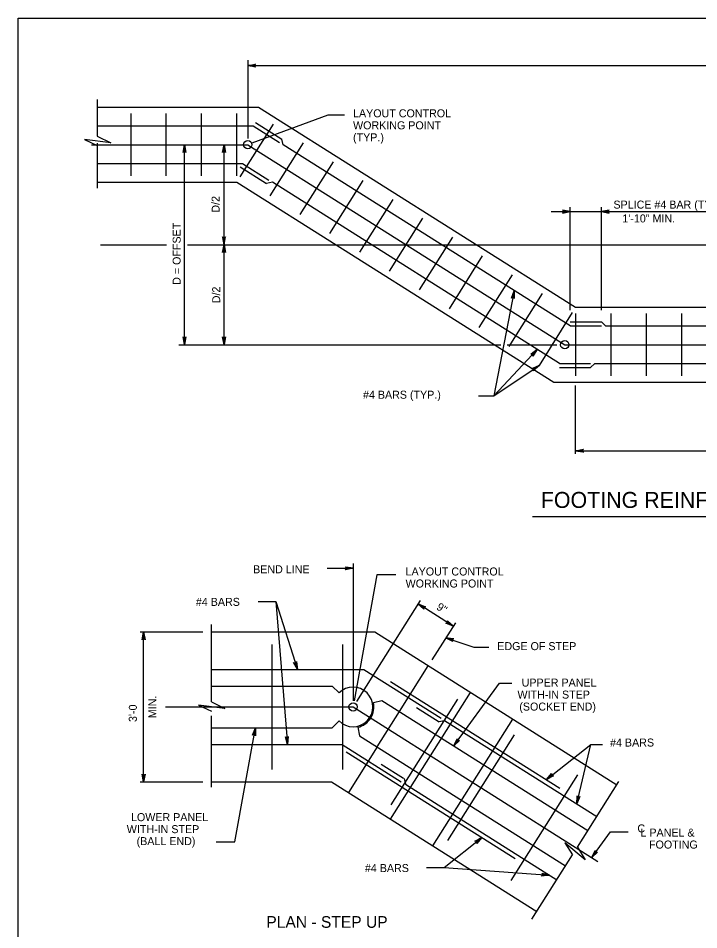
# Model space of a CAD drawing. Extents: x 3385 to 6532, y -616 to 1166.
# Drawn here: x 4642.3 to 4903.8, y -387.3 to -37.3 of the extents above; entities that cross this region are included whole.
import ezdxf

# ---------------------------------------------------------------- set-up
doc = ezdxf.new("R2010")
doc.units = 0
doc.layers.add('1', color=7, linetype='Continuous')
doc.layers.add('2', color=7, linetype='Continuous')

msp = doc.modelspace()

# ---------------------------------------------------------------- linework, layer by layer
at = {"layer": '1'}
for p, q in [((4730.55, -53.39), (4730.55, -83.46)), ((4730.55, -55.48), (5262.17, -55.48)), ((4672.73, -68.46), (4672.73, -82.65)), ((4672.73, -71.46), (4734.71, -71.46)), ((4734.71, -71.46), (4856.52, -148.26)), ((4685.68, -97.86), (4685.68, -73.86)), ((4699.25, -97.86), (4699.25, -73.86)), ((4712.82, -97.86), (4712.82, -73.86)), ((4726.39, -97.86), (4726.39, -73.86)), ((4761.26, -74.48), (4732.05, -85.3)), ((4767.72, -74.48), (4761.26, -74.48)), ((4672.73, -78.66), (4732.63, -78.66)), ((4727.67, -98.23), (4740.47, -77.93)), ((4732.63, -78.66), (4742.78, -85.06)), ((4733.48, -77.3), (4743.64, -83.7)), ((4744.14, -85.91), (4743.64, -83.7)), ((4670.51, -85.86), (4730.55, -85.86)), ((4672.73, -85.29), (4672.73, -102.52)), ((4706.23, -162.66), (4706.23, -85.86)), ((4721.42, -162.66), (4721.42, -85.86)), ((4730.55, -85.86), (4852.36, -162.66)), ((4730.55, -85.86), (4730.55, -85.86)), ((4739.14, -105.46), (4751.94, -85.16)), ((4854.44, -155.46), (4744.14, -85.91)), ((4672.73, -93.06), (4728.47, -93.06)), ((4727.61, -94.41), (4737.77, -100.81)), ((4728.47, -93.06), (4738.62, -99.46)), ((4750.62, -112.7), (4763.42, -92.39)), ((4672.73, -100.26), (4726.39, -100.26)), ((4726.39, -100.26), (4848.2, -177.06)), ((4739.98, -100.31), (4737.77, -100.81)), ((4850.28, -169.86), (4739.98, -100.31)), ((4762.09, -119.93), (4774.89, -99.63)), ((4773.57, -127.17), (4786.37, -106.86)), ((4847.16, -111.55), (4932.51, -111.55)), ((4854.44, -149.35), (4854.44, -109.88)), ((4866.44, -149.35), (4866.44, -109.88)), ((4785.04, -134.4), (4797.84, -114.1)), ((4796.51, -141.64), (4809.31, -121.33)), ((4673.94, -124.26), (4699.26, -124.26)), ((4707.43, -124.26), (5285.01, -124.26)), ((4807.99, -148.87), (4820.79, -128.57)), ((4819.46, -156.1), (4832.26, -135.8)), ((4832.96, -141.91), (4825.08, -182.24)), ((4830.94, -163.34), (4843.74, -143.04)), ((4855.24, -150.29), (4842.44, -170.59)), ((4856.52, -148.26), (4992.2, -148.26)), ((4854.44, -153.86), (4866.44, -153.86)), ((4856.52, -150.66), (4856.52, -174.66)), ((4868.04, -155.46), (4866.44, -153.86)), ((4870.08, -150.66), (4870.08, -174.66)), ((4883.65, -150.66), (4883.65, -174.66)), ((4897.21, -150.66), (4897.21, -174.66)), ((4854.44, -155.46), (4866.44, -155.46)), ((4868.04, -155.46), (4994.28, -155.46)), ((4704, -162.66), (4827.79, -162.66)), ((4825.08, -182.24), (4841.73, -164.47)), ((4830.2, -162.66), (4849.32, -162.66)), ((4852.36, -162.66), (4996.36, -162.66)), ((4852.36, -162.66), (4852.36, -162.66)), ((4825.08, -182.24), (4842.44, -170.59)), ((4850.28, -169.86), (4862.28, -169.86)), ((4850.28, -171.46), (4862.28, -171.46)), ((4863.88, -169.86), (4862.28, -171.46)), ((4863.88, -169.86), (4998.44, -169.86)), ((4848.2, -177.06), (5000.52, -177.06)), ((4856.52, -204.62), (4856.52, -178.37)), ((4819.25, -182.24), (4825.08, -182.24)), ((4856.52, -203.38), (4992.2, -203.38)), ((4839.99, -228.57), (5138.02, -228.57)), ((4761.01, -248.48), (4771.01, -248.48)), ((4771.01, -246.71), (4771.01, -299.34)), ((4780.13, -251.06), (4771.43, -299.38)), ((4787.47, -251.06), (4780.13, -251.06)), ((4734.54, -261.31), (4741.35, -261.31)), ((4741.35, -261.31), (4745.78, -316.14)), ((4741.35, -261.31), (4749.6, -287.34)), ((4796.78, -260.86), (4772.29, -299.71)), ((4809.49, -270.71), (4795.95, -262.17)), ((4810.32, -269.39), (4801.3, -283.69)), ((4689.15, -272.94), (4713.23, -272.94)), ((4690.54, -330.54), (4690.54, -272.94)), ((4716.55, -299.84), (4716.55, -270.06)), ((4716.55, -272.94), (4779.33, -272.94)), ((4779.33, -272.94), (4872.36, -331.59)), ((4806.65, -275.15), (4817.41, -278.73)), ((4739.97, -325.74), (4739.97, -277.74)), ((4767.11, -325.74), (4767.11, -277.74)), ((4817.41, -278.73), (4823.12, -278.73)), ((4788.81, -303.5), (4799.9, -285.91)), ((4716.55, -287.34), (4775.17, -287.34)), ((4775.17, -287.34), (4804.87, -306.07)), ((4716.55, -293.74), (4763.01, -293.74)), ((4763.01, -293.74), (4765.63, -296.37)), ((4785.43, -291.91), (4850.4, -332.87)), ((4809.69, -316.66), (4827.21, -292.59)), ((4827.21, -292.59), (4832.03, -292.59)), ((4785.42, -344.88), (4816.14, -296.15)), ((4778.81, -299.97), (4782.04, -299.24)), ((4782.05, -299.24), (4861.24, -349.17)), ((4785.6, -339.32), (4811.2, -298.71)), ((4698.94, -301.74), (4771.01, -301.74)), ((4771.01, -301.74), (4865.08, -361.05)), ((4771.01, -301.74), (4771.01, -301.74)), ((4780.27, -317.05), (4788.81, -303.5)), ((4795.43, -302), (4804.02, -307.42)), ((4716.55, -332.53), (4716.55, -305.09)), ((4763.01, -309.74), (4765.63, -307.12)), ((4801.66, -355.12), (4832.39, -306.39)), ((4803.99, -307.39), (4806.19, -306.9)), ((4806.19, -306.9), (4864.66, -343.76)), ((4716.55, -309.74), (4763.01, -309.74)), ((4725.54, -353.54), (4733.45, -309.74)), ((4772.78, -309.54), (4773.51, -312.78)), ((4773.51, -312.78), (4852.68, -362.7)), ((4807.38, -353.05), (4832.98, -312.44)), ((4716.55, -316.14), (4766.85, -316.14)), ((4766.85, -316.14), (4789.51, -330.43)), ((4780.27, -317.05), (4769.18, -334.64)), ((4845.27, -329.64), (4862.37, -316.15)), ((4856.95, -338.9), (4862.37, -316.15)), ((4862.37, -316.15), (4866.87, -316.15)), ((4768.35, -318.99), (4833.32, -359.95)), ((4781.77, -323.67), (4790.36, -329.08)), ((4831.75, -368.41), (4857.35, -327.8)), ((4689.15, -330.54), (4713.23, -330.54)), ((4716.55, -330.54), (4762.69, -330.54)), ((4762.69, -330.54), (4841.56, -380.27)), ((4790.61, -329.24), (4791.11, -331.44)), ((4791.11, -331.44), (4849.26, -368.1)), ((4857.19, -355.57), (4873.11, -330.4)), ((4862.76, -359.59), (4869.94, -349.71)), ((4869.94, -349.71), (4876.71, -349.71)), ((4805.96, -363.37), (4820.53, -351.88)), ((4718.41, -353.54), (4725.54, -353.54)), ((4839.72, -383.19), (4855.31, -358.54)), ((4799.15, -363.37), (4805.96, -363.37)), ((4805.96, -363.37), (4846.41, -366.31))]:
    msp.add_line(p, q, dxfattribs=at)
for points in [[(4730.55, -55.48), (4733.53, -54.92), (4733.3, -55.08), (4733.18, -55.28), (4733.15, -55.48), (4733.18, -55.68), (4733.3, -55.88), (4733.53, -56.04), (4730.55, -55.48), (4733.3, -55.88), (4733.18, -55.68), (4730.55, -55.48), (4733.15, -55.48), (4733.18, -55.28), (4730.55, -55.48), (4733.3, -55.08)], [(4672.73, -82.65), (4677.92, -85.19), (4667.77, -83.81), (4672.73, -86.17)], [(4706.23, -85.86), (4706.79, -88.84), (4706.63, -88.61), (4706.43, -88.49), (4706.23, -88.46), (4706.03, -88.49), (4705.83, -88.61), (4705.67, -88.84), (4706.23, -85.86), (4705.83, -88.61), (4706.03, -88.49), (4706.23, -85.86), (4706.23, -88.46), (4706.43, -88.49), (4706.23, -85.86), (4706.63, -88.61)], [(4721.42, -85.86), (4721.98, -88.84), (4721.82, -88.61), (4721.62, -88.49), (4721.42, -88.46), (4721.22, -88.49), (4721.02, -88.61), (4720.86, -88.84), (4721.42, -85.86), (4721.02, -88.61), (4721.22, -88.49), (4721.42, -85.86), (4721.42, -88.46), (4721.62, -88.49), (4721.42, -85.86), (4721.82, -88.61)], [(4854.44, -111.55), (4851.46, -110.99), (4851.69, -111.15), (4851.81, -111.35), (4851.84, -111.55), (4851.81, -111.75), (4851.69, -111.95), (4851.46, -112.11), (4854.44, -111.55), (4851.69, -111.95), (4851.81, -111.75), (4854.44, -111.55), (4851.84, -111.55), (4851.81, -111.35), (4854.44, -111.55), (4851.69, -111.15)], [(4866.44, -111.55), (4869.43, -112.11), (4869.2, -111.95), (4869.08, -111.75), (4869.04, -111.55), (4869.08, -111.35), (4869.2, -111.15), (4869.43, -110.99), (4866.44, -111.55), (4869.2, -111.15), (4869.08, -111.35), (4866.44, -111.55), (4869.04, -111.55), (4869.08, -111.75), (4866.44, -111.55), (4869.2, -111.95)], [(4721.42, -124.26), (4721.98, -121.28), (4721.82, -121.51), (4721.62, -121.62), (4721.42, -121.66), (4721.22, -121.62), (4721.02, -121.51), (4720.86, -121.28), (4721.42, -124.26), (4721.02, -121.51), (4721.22, -121.62), (4721.42, -124.26), (4721.42, -121.66), (4721.62, -121.62), (4721.42, -124.26), (4721.82, -121.51)], [(4721.42, -124.26), (4721.98, -127.24), (4721.82, -127.01), (4721.62, -126.89), (4721.42, -126.86), (4721.22, -126.89), (4721.02, -127.01), (4720.86, -127.24), (4721.42, -124.26), (4721.02, -127.01), (4721.22, -126.89), (4721.42, -124.26), (4721.42, -126.86), (4721.62, -126.89), (4721.42, -124.26), (4721.82, -127.01)], [(4832.96, -141.91), (4832.93, -144.95), (4832.88, -144.82), (4832.82, -144.69), (4832.73, -144.61), (4832.65, -144.54), (4832.55, -144.5), (4832.46, -144.47), (4832.36, -144.46), (4832.26, -144.46), (4832.15, -144.5), (4832.04, -144.54), (4831.94, -144.64), (4831.84, -144.73), (4832.96, -141.91), (4831.94, -144.64), (4832.04, -144.54), (4832.96, -141.91), (4832.15, -144.5), (4832.26, -144.46), (4832.96, -141.91), (4832.36, -144.46), (4832.46, -144.47), (4832.96, -141.91), (4832.55, -144.5), (4832.65, -144.54), (4832.96, -141.91), (4832.73, -144.61), (4832.82, -144.69), (4832.96, -141.91), (4832.88, -144.82)], [(4706.23, -162.66), (4705.67, -159.68), (4705.83, -159.91), (4706.03, -160.02), (4706.23, -160.06), (4706.43, -160.02), (4706.63, -159.91), (4706.79, -159.68), (4706.23, -162.66), (4706.63, -159.91), (4706.43, -160.02), (4706.23, -162.66), (4706.23, -160.06), (4706.03, -160.02), (4706.23, -162.66), (4705.83, -159.91)], [(4721.42, -162.66), (4720.86, -159.68), (4721.02, -159.91), (4721.22, -160.02), (4721.42, -160.06), (4721.62, -160.02), (4721.82, -159.91), (4721.98, -159.68), (4721.42, -162.66), (4721.82, -159.91), (4721.62, -160.02), (4721.42, -162.66), (4721.42, -160.06), (4721.22, -160.02), (4721.42, -162.66), (4721.02, -159.91)], [(4841.73, -164.47), (4840.1, -167.03), (4840.12, -166.89), (4840.14, -166.75), (4840.11, -166.64), (4840.08, -166.53), (4840.02, -166.45), (4839.96, -166.37), (4839.87, -166.31), (4839.79, -166.26), (4839.67, -166.23), (4839.56, -166.21), (4839.42, -166.24), (4839.29, -166.26), (4841.73, -164.47), (4839.42, -166.24), (4839.56, -166.21), (4841.73, -164.47), (4839.67, -166.23), (4839.79, -166.26), (4841.73, -164.47), (4839.87, -166.31), (4839.96, -166.37), (4841.73, -164.47), (4840.02, -166.45), (4840.08, -166.53), (4841.73, -164.47), (4840.11, -166.64), (4840.14, -166.75), (4841.73, -164.47), (4840.12, -166.89)], [(4842.44, -170.59), (4840.27, -172.72), (4840.38, -172.46), (4840.36, -172.22), (4840.28, -172.04), (4840.14, -171.89), (4839.93, -171.79), (4839.65, -171.79), (4842.44, -170.59), (4839.93, -171.79), (4840.14, -171.89), (4842.44, -170.59), (4840.28, -172.04), (4840.36, -172.22), (4842.44, -170.59), (4840.38, -172.46)], [(4856.52, -203.38), (4859.5, -202.82), (4859.27, -202.98), (4859.15, -203.18), (4859.12, -203.38), (4859.15, -203.58), (4859.27, -203.78), (4859.5, -203.93), (4856.52, -203.38), (4859.27, -203.78), (4859.15, -203.58), (4856.52, -203.38), (4859.12, -203.38), (4859.15, -203.18), (4856.52, -203.38), (4859.27, -202.98)], [(4771.01, -248.48), (4768.03, -249.04), (4768.25, -248.88), (4768.37, -248.68), (4768.41, -248.48), (4768.37, -248.28), (4768.25, -248.08), (4768.03, -247.92), (4771.01, -248.48), (4768.25, -248.08), (4768.37, -248.28), (4771.01, -248.48), (4768.41, -248.48), (4768.37, -248.68), (4771.01, -248.48), (4768.25, -248.88)], [(4795.95, -262.17), (4798.77, -263.29), (4798.5, -263.3), (4798.29, -263.41), (4798.15, -263.56), (4798.07, -263.75), (4798.07, -263.98), (4798.18, -264.24), (4795.95, -262.17), (4798.07, -263.98), (4798.07, -263.75), (4795.95, -262.17), (4798.15, -263.56), (4798.29, -263.41), (4795.95, -262.17), (4798.5, -263.3)], [(4809.49, -270.71), (4806.67, -269.59), (4806.95, -269.58), (4807.15, -269.47), (4807.29, -269.32), (4807.37, -269.13), (4807.37, -268.9), (4807.26, -268.64), (4809.49, -270.71), (4807.37, -268.9), (4807.37, -269.13), (4809.49, -270.71), (4807.29, -269.32), (4807.15, -269.47), (4809.49, -270.71), (4806.95, -269.58)], [(4690.54, -272.94), (4691.09, -275.92), (4690.94, -275.69), (4690.74, -275.57), (4690.54, -275.54), (4690.34, -275.57), (4690.14, -275.69), (4689.98, -275.92), (4690.54, -272.94), (4690.14, -275.69), (4690.34, -275.57), (4690.54, -272.94), (4690.54, -275.54), (4690.74, -275.57), (4690.54, -272.94), (4690.94, -275.69)], [(4806.65, -275.15), (4809.66, -275.56), (4809.52, -275.6), (4809.39, -275.64), (4809.3, -275.71), (4809.21, -275.79), (4809.17, -275.88), (4809.12, -275.97), (4809.1, -276.07), (4809.09, -276.17), (4809.11, -276.28), (4809.14, -276.4), (4809.22, -276.51), (4809.3, -276.62), (4806.65, -275.15), (4809.22, -276.51), (4809.14, -276.4), (4806.65, -275.15), (4809.11, -276.28), (4809.09, -276.17), (4806.65, -275.15), (4809.1, -276.07), (4809.12, -275.97), (4806.65, -275.15), (4809.17, -275.88), (4809.21, -275.79), (4806.65, -275.15), (4809.3, -275.71), (4809.39, -275.64), (4806.65, -275.15), (4809.52, -275.6)], [(4749.6, -287.34), (4748.16, -284.67), (4748.38, -284.84), (4748.61, -284.89), (4748.81, -284.86), (4748.99, -284.77), (4749.15, -284.59), (4749.23, -284.33), (4749.6, -287.34), (4749.15, -284.59), (4748.99, -284.77), (4749.6, -287.34), (4748.81, -284.86), (4748.61, -284.89), (4749.6, -287.34), (4748.38, -284.84)], [(4716.55, -299.84), (4721.73, -302.38), (4711.59, -301), (4716.55, -303.36)], [(4733.45, -309.74), (4733.47, -312.78), (4733.35, -312.52), (4733.18, -312.37), (4732.99, -312.3), (4732.78, -312.3), (4732.57, -312.38), (4732.37, -312.58), (4733.45, -309.74), (4732.57, -312.38), (4732.78, -312.3), (4733.45, -309.74), (4732.99, -312.3), (4733.18, -312.37), (4733.45, -309.74), (4733.35, -312.52)], [(4745.78, -316.14), (4744.98, -313.21), (4745.16, -313.43), (4745.37, -313.53), (4745.57, -313.55), (4745.77, -313.5), (4745.96, -313.36), (4746.1, -313.12), (4745.78, -316.14), (4745.96, -313.36), (4745.77, -313.5), (4745.78, -316.14), (4745.57, -313.55), (4745.37, -313.53), (4745.78, -316.14), (4745.16, -313.43)], [(4809.69, -316.66), (4810.99, -313.92), (4810.98, -314.2), (4811.07, -314.41), (4811.22, -314.56), (4811.4, -314.65), (4811.63, -314.67), (4811.89, -314.58), (4809.69, -316.66), (4811.63, -314.67), (4811.4, -314.65), (4809.69, -316.66), (4811.22, -314.56), (4811.07, -314.41), (4809.69, -316.66), (4810.98, -314.2)], [(4690.54, -330.54), (4689.98, -327.56), (4690.14, -327.79), (4690.34, -327.91), (4690.54, -327.94), (4690.74, -327.91), (4690.94, -327.79), (4691.09, -327.56), (4690.54, -330.54), (4690.94, -327.79), (4690.74, -327.91), (4690.54, -330.54), (4690.54, -327.94), (4690.34, -327.91), (4690.54, -330.54), (4690.14, -327.79)], [(4845.27, -329.64), (4847.26, -327.35), (4847.18, -327.62), (4847.21, -327.85), (4847.31, -328.03), (4847.46, -328.16), (4847.68, -328.25), (4847.96, -328.23), (4845.27, -329.64), (4847.68, -328.25), (4847.46, -328.16), (4845.27, -329.64), (4847.31, -328.03), (4847.21, -327.85), (4845.27, -329.64), (4847.18, -327.62)], [(4856.95, -338.9), (4857.1, -335.87), (4857.2, -336.13), (4857.37, -336.29), (4857.55, -336.37), (4857.75, -336.39), (4857.98, -336.32), (4858.18, -336.13), (4856.95, -338.9), (4857.98, -336.32), (4857.75, -336.39), (4856.95, -338.9), (4857.55, -336.37), (4857.37, -336.29), (4856.95, -338.9), (4857.2, -336.13)], [(4820.53, -351.88), (4818.53, -354.17), (4818.61, -353.9), (4818.58, -353.67), (4818.49, -353.49), (4818.33, -353.36), (4818.12, -353.28), (4817.84, -353.29), (4820.53, -351.88), (4818.12, -353.28), (4818.33, -353.36), (4820.53, -351.88), (4818.49, -353.49), (4818.58, -353.67), (4820.53, -351.88), (4818.61, -353.9)], [(4857.19, -355.57), (4860.22, -360.49), (4852.38, -353.9), (4855.31, -358.55)], [(4862.76, -359.59), (4864.06, -356.85), (4864.05, -357.13), (4864.14, -357.34), (4864.29, -357.48), (4864.47, -357.57), (4864.7, -357.6), (4864.96, -357.5), (4862.76, -359.59), (4864.7, -357.6), (4864.47, -357.57), (4862.76, -359.59), (4864.29, -357.48), (4864.14, -357.34), (4862.76, -359.59), (4864.05, -357.13)], [(4846.41, -366.31), (4843.4, -366.65), (4843.64, -366.51), (4843.77, -366.31), (4843.82, -366.12), (4843.8, -365.92), (4843.7, -365.71), (4843.48, -365.53), (4846.41, -366.31), (4843.7, -365.71), (4843.8, -365.92), (4846.41, -366.31), (4843.82, -366.12), (4843.77, -366.31), (4846.41, -366.31), (4843.64, -366.51)]]:
    msp.add_lwpolyline(points, dxfattribs=at)
for centre in [(4730.55, -85.86), (4852.36, -162.66), (4771.01, -301.74)]:
    msp.add_circle(centre, 1.6, dxfattribs=at)
for radius, start, end in [(7.6, 225, 135), (8, 282.7683, 12.7708)]:
    msp.add_arc((4771.01, -301.74), radius, start, end, dxfattribs=at)
at = {"layer": '2'}
for p, q in [((4642.34, -601.31), (4642.34, -37.31)), ((4642.34, -37.31), (5428.34, -37.31))]:
    msp.add_line(p, q, dxfattribs=at)

# ---------------------------------------------------------------- texts
at = {"layer": '1'}
for s, height, p in [('LAYOUT CONTROL', 3.0721, (4770.99, -75.35)), ('WORKING POINT', 3.0721, (4770.99, -79.96)), ('(TYP.)', 3.072, (4770.99, -84.57)), ('SPLICE #4 BAR (TYP.)', 3.0721, (4871.04, -110.4)), ('   1\'-10" MIN.', 3.0721, (4871.04, -115.72)), ('#4 BARS (TYP.)', 3.0721, (4774.82, -183.4)), ('FOOTING REINFORCEMENT LAYOUT FOR STANDARD PANELS', 6.144, (4843.14, -225.33)), ('BEND LINE', 3.072, (4732.59, -250.42)), ('LAYOUT CONTROL', 3.0721, (4791.18, -251.27)), ('WORKING POINT', 3.0721, (4791.18, -255.88)), ('#4 BARS', 3.072, (4710.6, -262.93)), ('EDGE OF STEP', 3.0721, (4826.41, -279.93)), ('UPPER PANEL', 3.0721, (4835.78, -293.92)), ('WITH-IN STEP', 3.0721, (4834.16, -298.53)), ('(SOCKET END)', 3.0721, (4834.87, -303.14)), ('#4 BARS', 3.072, (4869.75, -316.94)), ('LOWER PANEL', 3.0721, (4685.67, -345.59)), ('WITH-IN STEP', 3.0721, (4684.05, -350.2)), ('C', 3.07, (4880.24, -349.91)), ('L PANEL &', 3.072, (4881.43, -351.5)), ('(BALL END)', 3.072, (4687.83, -354.8)), ('FOOTING', 3.072, (4884.71, -356.11)), ('#4 BARS', 3.072, (4775.55, -365.13)), ('PLAN - STEP UP', 4.4801, (4737.68, -386.54))]:
    msp.add_text(s, height=height, dxfattribs=at).set_placement(p)
for s, rotation, p in [('D/2', 90, (4719.73, -111.96)), ('D = OFFSET', 90, (4704.75, -139.67)), ('D/2', 90, (4719.95, -146.74)), ('9"', 327.769, (4802.76, -264.09)), ("3'-0", 90, (4687.91, -307.52)), ('MIN.', 90, (4695.38, -306.07))]:
    msp.add_text(s, height=3.072, rotation=rotation, dxfattribs=at).set_placement(p)

doc.saveas('drawing.dxf')
